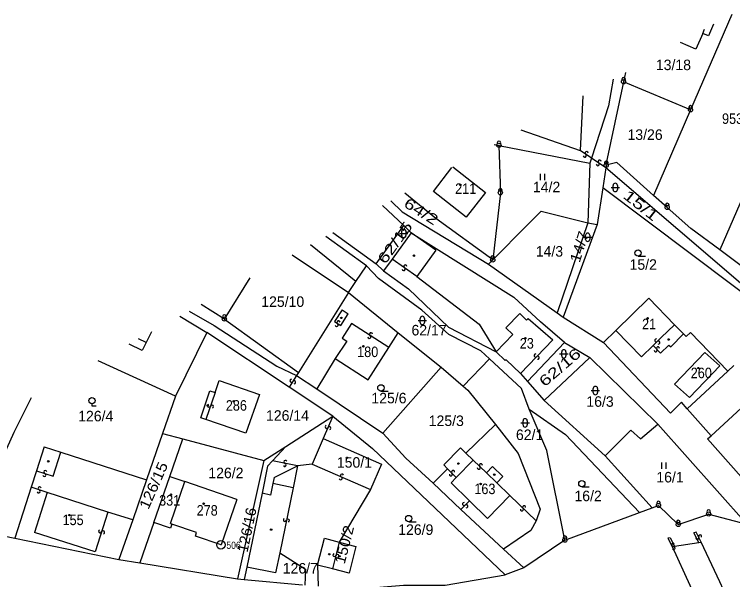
# Model space of a CAD drawing. Extents: x -680102 to -677253, y -1007548 to -1006096.
# Drawn here: x -679928 to -679757, y -1007092.8 to -1006958.4 of the extents above; entities that cross this region are included whole.
import ezdxf
from ezdxf.enums import TextEntityAlignment as Align

# ---------------------------------------------------------------- set-up
doc = ezdxf.new("R2010")
doc.units = 0
for name, color, linetype, lineweight in [('1', 7, 'Continuous', 25), ('24', 7, 'Continuous', 25), ('25', 7, 'Continuous', 25), ('4', 7, 'Continuous', 25)]:
    doc.layers.add(name, color=color, linetype=linetype, lineweight=lineweight)
for name, color, linetype in [('17', 7, 'Continuous'), ('18', 7, 'Continuous'), ('19', 7, 'Continuous')]:
    doc.layers.add(name, color=color, linetype=linetype)

msp = doc.modelspace()

# ---------------------------------------------------------------- linework, layer by layer
at = {"layer": '1'}
for p, q in [((-679757.23, -1006958.42), (-679767.04, -1006981.12)), ((-679765.74, -1006966.67), (-679769.4, -1006965.07)), ((-679739.2, -1006966.09), (-679760.08, -1007014.44)), ((-679782.51, -1006972.23), (-679782.98, -1006974.45)), ((-679782.98, -1006974.45), (-679787.08, -1006993.84)), ((-679785.46, -1006973.85), (-679786.54, -1006980.16)), ((-679767.04, -1006981.12), (-679782.98, -1006974.45)), ((-679792.7, -1006977.8), (-679793.34, -1006990.83)), ((-679767.04, -1006981.12), (-679775.83, -1007001.46)), ((-679807.4, -1006985.84), (-679793.34, -1006990.83)), ((-679791.04, -1006993.81), (-679791.46, -1007007.98)), ((-679828.25, -1007000.54), (-679823.88, -1006994.85)), ((-679787.16, -1006994.88), (-679787.94, -1006999.66)), ((-679787.11, -1006994.29), (-679787.16, -1006994.88)), ((-679745.57, -1007030.62), (-679787.16, -1006994.88)), ((-679827.65, -1007006.94), (-679835.04, -1007000.94)), ((-679802.58, -1007005.2), (-679805.94, -1007008.58)), ((-679802.58, -1007005.2), (-679791.46, -1007007.98)), ((-679767, -1007009.31), (-679772.59, -1007004.34)), ((-679814.11, -1007016.82), (-679827.65, -1007006.94)), ((-679841.89, -1007017.75), (-679835.31, -1007008.64)), ((-679805.94, -1007008.58), (-679814.11, -1007016.82)), ((-679791.46, -1007007.98), (-679798.76, -1007029.42)), ((-679789.24, -1007008.41), (-679797.34, -1007030.43)), ((-679791.46, -1007007.98), (-679789.24, -1007008.41)), ((-679852.14, -1007010.29), (-679841.89, -1007017.75)), ((-679844.15, -1007018.19), (-679853.83, -1007011.21)), ((-679846.67, -1007021.91), (-679857.49, -1007013.22)), ((-679841.89, -1007017.75), (-679840.1, -1007019.44)), ((-679814.11, -1007016.82), (-679815.13, -1007017.85)), ((-679877.98, -1007030.87), (-679871.82, -1007021.05)), ((-679848.46, -1007024.55), (-679836.61, -1007034.16)), ((-679776.99, -1007025.9), (-679784.84, -1007033.56)), ((-679770.86, -1007032.24), (-679776.99, -1007025.9)), ((-679877.98, -1007030.87), (-679883.47, -1007027.42)), ((-679886.39, -1007029.01), (-679880.44, -1007032.37)), ((-679877.98, -1007030.87), (-679860.36, -1007043.55)), ((-679797.34, -1007030.43), (-679787.78, -1007036.43)), ((-679880.44, -1007032.37), (-679865.47, -1007042.07)), ((-679797.03, -1007036.49), (-679802.76, -1007031.54)), ((-679768.73, -1007034.4), (-679770.86, -1007032.24)), ((-679836.61, -1007034.16), (-679826.39, -1007042.33)), ((-679784.84, -1007033.56), (-679787.78, -1007036.43)), ((-679768.1, -1007035.04), (-679768.73, -1007034.4)), ((-679767.07, -1007034.04), (-679768.1, -1007035.04)), ((-679758.16, -1007043.25), (-679767.07, -1007034.04)), ((-679797.03, -1007036.49), (-679805.84, -1007045.71)), ((-679797.03, -1007036.49), (-679790.99, -1007039.99)), ((-679771.83, -1007053.22), (-679787.78, -1007036.43)), ((-679811.13, -1007040.76), (-679813.31, -1007038.67)), ((-679790.99, -1007039.99), (-679801.85, -1007050.21)), ((-679770.82, -1007046.36), (-679763.61, -1007038.83)), ((-679851.62, -1007040.28), (-679855.97, -1007047.43)), ((-679851.62, -1007040.28), (-679843.76, -1007045.29)), ((-679821.17, -1007046.83), (-679814.91, -1007040.34)), ((-679865.47, -1007042.07), (-679860.84, -1007044.32)), ((-679840.27, -1007058.01), (-679826.39, -1007042.33)), ((-679860.84, -1007044.32), (-679855.97, -1007047.43)), ((-679767.31, -1007049.52), (-679770.82, -1007046.36)), ((-679855.97, -1007047.43), (-679840.27, -1007058.01)), ((-679805.44, -1007052.28), (-679807.27, -1007047.36)), ((-679889.6, -1007049.19), (-679892.68, -1007058.07)), ((-679769.21, -1007050.67), (-679771.83, -1007053.22)), ((-679767.86, -1007052.2), (-679769.21, -1007050.67)), ((-679801.21, -1007062.13), (-679805.44, -1007052.28)), ((-679805.44, -1007052.28), (-679796.8, -1007058.31)), ((-679852.14, -1007054), (-679842.76, -1007061.63)), ((-679813.45, -1007055.98), (-679820.49, -1007062.77)), ((-679778.92, -1007059.36), (-679774.85, -1007055.84)), ((-679892.68, -1007058.07), (-679896.5, -1007069.13)), ((-679892.68, -1007058.07), (-679887.85, -1007059.36)), ((-679840.27, -1007058.01), (-679834.81, -1007063.96)), ((-679779.22, -1007076.89), (-679796.8, -1007058.31)), ((-679781.21, -1007057.32), (-679787.33, -1007063.44)), ((-679778.92, -1007059.36), (-679781.21, -1007057.32)), ((-679890.96, -1007068.3), (-679887.85, -1007059.36)), ((-679887.85, -1007059.36), (-679868.58, -1007064.53)), ((-679854.48, -1007059.32), (-679857.12, -1007065.42)), ((-679854.48, -1007059.32), (-679840.61, -1007065.35)), ((-679920.86, -1007061.23), (-679922.71, -1007066.96)), ((-679842.76, -1007061.63), (-679811.14, -1007091.68)), ((-679825.73, -1007065.53), (-679821.77, -1007061.51)), ((-679821.77, -1007061.51), (-679820.49, -1007062.77)), ((-679796.94, -1007083.44), (-679801.21, -1007062.13)), ((-679868.58, -1007064.53), (-679874.84, -1007092.69)), ((-679857.12, -1007065.42), (-679860.55, -1007065.82)), ((-679840.61, -1007065.35), (-679843.2, -1007071.44)), ((-679824.85, -1007066.5), (-679825.73, -1007065.53)), ((-679867.68, -1007065.87), (-679869.01, -1007072.3)), ((-679860.55, -1007065.82), (-679861.62, -1007070.99)), ((-679824.85, -1007066.5), (-679828.32, -1007069.93)), ((-679896.5, -1007069.13), (-679899.8, -1007078.65)), ((-679890.8, -1007079.51), (-679887.36, -1007069.52)), ((-679875.03, -1007073.76), (-679887.36, -1007069.52)), ((-679866.41, -1007070.01), (-679866.97, -1007072.72)), ((-679861.62, -1007070.99), (-679866.41, -1007070.01)), ((-679866.97, -1007072.72), (-679869.01, -1007072.3)), ((-679843.2, -1007071.44), (-679850.63, -1007083.92)), ((-679776.19, -1007075.77), (-679774.66, -1007075.2)), ((-679821.69, -1007076.17), (-679811.59, -1007085.56)), ((-679899.8, -1007078.65), (-679903.06, -1007088.07)), ((-679894.78, -1007079.26), (-679898.13, -1007088.88)), ((-679890.8, -1007079.51), (-679890.45, -1007079.63)), ((-679805.07, -1007081.19), (-679811.59, -1007085.56)), ((-679811.59, -1007085.56), (-679806.75, -1007090.06)), ((-679864.82, -1007086.46), (-679865.84, -1007091.22)), ((-679864.82, -1007086.46), (-679858.64, -1007090.34)), ((-679903.06, -1007088.07), (-679898.13, -1007088.88)), ((-679898.13, -1007088.88), (-679874.84, -1007092.69)), ((-679855.79, -1007089.38), (-679855.63, -1007094.38)), ((-679865.84, -1007091.22), (-679872.6, -1007089.85)), ((-679858.64, -1007090.34), (-679858.85, -1007094.13))]:
    msp.add_line(p, q, dxfattribs=at)
for points in [[(-679761.54, -1006960.77), (-679762.75, -1006963.55), (-679764.12, -1006962.95), (-679765.74, -1006966.67)], [(-679786.54, -1006980.16), (-679790.64, -1006992.6), (-679791.04, -1006993.81)], [(-679812.64, -1006989.57), (-679812.29, -1007000.85), (-679814.11, -1007016.82)], [(-679813.81, -1006989.34), (-679812.64, -1006989.57), (-679791.04, -1006993.81)], [(-679784.58, -1006993.66), (-679787.11, -1006994.29), (-679787.08, -1006993.84)], [(-679772.59, -1007004.34), (-679775.83, -1007001.46), (-679784.58, -1006993.66)], [(-679823.61, -1006994.7), (-679815.81, -1007000.75), (-679820.44, -1007006.65), (-679828.25, -1007000.54)], [(-679736.11, -1007038.63), (-679787.94, -1006999.66), (-679789.24, -1007008.41)], [(-679840.34, -1007003.84), (-679835.31, -1007008.64), (-679833.52, -1007010.34)], [(-679838.34, -1007002.75), (-679835.67, -1007005.4), (-679815.13, -1007017.85)], [(-679833.52, -1007010.34), (-679838.08, -1007016.6), (-679840.1, -1007019.44)], [(-679833.52, -1007010.34), (-679809.11, -1007025.65), (-679802.76, -1007031.54)], [(-679751.46, -1007020.82), (-679760.08, -1007014.44), (-679767, -1007009.31)], [(-679861.83, -1007015.59), (-679848.46, -1007024.55), (-679860.36, -1007043.55), (-679860.84, -1007044.32)], [(-679848.46, -1007024.55), (-679846.67, -1007021.91), (-679844.15, -1007018.19)], [(-679816.96, -1007038.45), (-679824.59, -1007034.54), (-679830.95, -1007028.76), (-679841.32, -1007021.22), (-679844.15, -1007018.19)], [(-679840.1, -1007019.44), (-679834.14, -1007023.72), (-679824.68, -1007032.81), (-679813.31, -1007038.67)], [(-679815.13, -1007017.85), (-679798.76, -1007029.42), (-679797.34, -1007030.43)], [(-679888.55, -1007030.19), (-679882.19, -1007034.04), (-679889.6, -1007049.19), (-679908.05, -1007040.85)], [(-679895.36, -1007033.91), (-679896.63, -1007036.46), (-679897.58, -1007038.35), (-679900.66, -1007036.81)], [(-679852.14, -1007054), (-679862.57, -1007047.08), (-679882.19, -1007034.04)], [(-679843.76, -1007045.29), (-679838.85, -1007037.65), (-679836.61, -1007034.16)], [(-679807.27, -1007047.36), (-679814.91, -1007040.34), (-679816.96, -1007038.45)], [(-679790.99, -1007039.99), (-679774.85, -1007055.84), (-679753.61, -1007079.63)], [(-679767.31, -1007049.52), (-679760.09, -1007042.03), (-679763.61, -1007038.83)], [(-679807.5, -1007043.83), (-679810.92, -1007040.55), (-679811.13, -1007040.76)], [(-679826.39, -1007042.33), (-679821.17, -1007046.83), (-679820.03, -1007047.81)], [(-679767.86, -1007052.2), (-679758.16, -1007043.25), (-679756.75, -1007041.95)], [(-679807.5, -1007043.83), (-679805.84, -1007045.71), (-679801.85, -1007050.21)], [(-679820.03, -1007047.81), (-679813.45, -1007055.98), (-679808.1, -1007062.88)], [(-679965.15, -1007072.06), (-679965.26, -1007072.39), (-679961.39, -1007073.5), (-679938.19, -1007080.24), (-679928.04, -1007057.75), (-679923.88, -1007049.51)], [(-679801.85, -1007050.21), (-679787.33, -1007063.44), (-679776.19, -1007075.77)], [(-679762.97, -1007059.37), (-679762.16, -1007058.62), (-679767.86, -1007052.2)], [(-679868.58, -1007064.53), (-679863.36, -1007061.18), (-679852.14, -1007054)], [(-679747.35, -1007070.09), (-679750.83, -1007073.05), (-679752.52, -1007071.14), (-679762.97, -1007059.37)], [(-679920.86, -1007061.23), (-679916.88, -1007062.52), (-679896.5, -1007069.13)], [(-679867.68, -1007065.87), (-679866.51, -1007064.6), (-679863.36, -1007061.18)], [(-679808.1, -1007062.88), (-679802.82, -1007076.1), (-679803.79, -1007078.88), (-679805.07, -1007081.19)], [(-679834.81, -1007063.96), (-679828.32, -1007069.93), (-679821.69, -1007076.17)], [(-679922.71, -1007066.96), (-679923.98, -1007070.89), (-679927.88, -1007082.96)], [(-679884.59, -1007081.64), (-679890.45, -1007079.63), (-679890.8, -1007080.63), (-679894.78, -1007079.26), (-679890.96, -1007068.3), (-679887.36, -1007069.52)], [(-679869.01, -1007072.3), (-679872.6, -1007089.85), (-679873.26, -1007092.83)], [(-679875.03, -1007073.76), (-679878.75, -1007084.58), (-679884.89, -1007082.51), (-679884.59, -1007081.64)], [(-679796.94, -1007083.44), (-679779.22, -1007076.89), (-679776.19, -1007075.77)], [(-679774.66, -1007075.2), (-679769.96, -1007079.73), (-679762.72, -1007077.25)], [(-679762.72, -1007077.25), (-679753.61, -1007079.63), (-679744.06, -1007082.12)], [(-679933.72, -1007081.76), (-679927.88, -1007082.96), (-679903.06, -1007088.07)], [(-679796.94, -1007083.44), (-679806.75, -1007090.06), (-679811.14, -1007091.68)], [(-679874.84, -1007092.69), (-679873.26, -1007092.83), (-679859.4, -1007094.09)], [(-679846.67, -1007095.09), (-679835.35, -1007094.16), (-679825.42, -1007094.12), (-679811.14, -1007091.68)]]:
    msp.add_lwpolyline(points, dxfattribs=at)
for points in [[(-679879.19, -1007045.47), (-679869.64, -1007048.78), (-679872.84, -1007058.03), (-679882.38, -1007054.8), (-679883.59, -1007054.39), (-679881.41, -1007047.94), (-679880.18, -1007048.36)], [(-679854.16, -1007083.02), (-679850.63, -1007083.92), (-679846.67, -1007084.94), (-679848.3, -1007091.3), (-679852.27, -1007090.28), (-679855.79, -1007089.38)]]:
    msp.add_lwpolyline(points, close=True, dxfattribs=at)
at = {"layer": '24'}
for centre, radius in [((-679782.98, -1006974.45), 0.5), ((-679782.98, -1006974.45), 0.022), ((-679767.04, -1006981.12), 0.5), ((-679767.04, -1006981.12), 0.022), ((-679812.64, -1006989.57), 0.5), ((-679812.64, -1006989.57), 0.022), ((-679787.11, -1006994.29), 0.5), ((-679787.11, -1006994.29), 0.022), ((-679812.29, -1007000.85), 0.5), ((-679812.29, -1007000.85), 0.022), ((-679772.59, -1007004.34), 0.5), ((-679772.59, -1007004.34), 0.022), ((-679814.11, -1007016.82), 0.5), ((-679814.11, -1007016.82), 0.022), ((-679877.98, -1007030.87), 0.5), ((-679877.98, -1007030.87), 0.022), ((-679774.66, -1007075.2), 0.5), ((-679774.66, -1007075.2), 0.022), ((-679762.72, -1007077.25), 0.5), ((-679762.72, -1007077.25), 0.022), ((-679769.96, -1007079.73), 0.5), ((-679769.96, -1007079.73), 0.022), ((-679878.81, -1007084.57), 1), ((-679796.94, -1007083.44), 0.5), ((-679796.94, -1007083.44), 0.022), ((-679878.81, -1007084.57), 0.032)]:
    msp.add_circle(centre, radius, dxfattribs=at)
for centre in [(-679782.981, -1006973.887), (-679767.041, -1006980.557), (-679812.641, -1006989.007), (-679787.111, -1006993.727), (-679812.291, -1007000.287), (-679772.591, -1007003.777), (-679814.111, -1007016.257), (-679877.981, -1007030.307), (-679774.661, -1007074.637), (-679762.721, -1007076.687), (-679769.961, -1007079.167), (-679796.941, -1007082.877)]:
    msp.add_arc(centre, 0.437, 328.35109, 209.97456, dxfattribs=at)
at = {"layer": '25'}
for p, q in [((-679802.737, -1006997.845), (-679802.737, -1006996.345)), ((-679801.703, -1006997.845), (-679801.703, -1006996.345)), ((-679785.96, -1006999.58), (-679783.96, -1006999.58)), ((-679785.46, -1007000.08), (-679785.46, -1006999.08)), ((-679784.46, -1006999.08), (-679784.46, -1007000.08)), ((-679836.28, -1007010.51), (-679834.28, -1007010.51)), ((-679835.78, -1007011.01), (-679835.78, -1007010.01)), ((-679834.78, -1007010.01), (-679834.78, -1007011.01)), ((-679792.02, -1007011.93), (-679792.02, -1007010.93)), ((-679791.02, -1007010.93), (-679791.02, -1007011.93)), ((-679792.52, -1007011.43), (-679790.52, -1007011.43)), ((-679779.52, -1007015.9), (-679777.77, -1007015.9)), ((-679831.88, -1007031.21), (-679829.88, -1007031.21)), ((-679831.38, -1007031.71), (-679831.38, -1007030.71)), ((-679830.38, -1007030.71), (-679830.38, -1007031.71)), ((-679798.19, -1007039.16), (-679796.19, -1007039.16)), ((-679797.69, -1007039.66), (-679797.69, -1007038.66)), ((-679796.69, -1007038.66), (-679796.69, -1007039.66)), ((-679840.73, -1007047.99), (-679838.98, -1007047.99)), ((-679790.68, -1007047.88), (-679788.68, -1007047.88)), ((-679790.18, -1007048.38), (-679790.18, -1007047.38)), ((-679789.18, -1007047.38), (-679789.18, -1007048.38)), ((-679806.9, -1007056.07), (-679806.9, -1007055.07)), ((-679805.9, -1007055.07), (-679805.9, -1007056.07)), ((-679807.4, -1007055.57), (-679805.4, -1007055.57)), ((-679773.877, -1007066.485), (-679773.877, -1007064.985)), ((-679772.843, -1007066.485), (-679772.843, -1007064.985)), ((-679792.91, -1007070.75), (-679791.16, -1007070.75)), ((-679834.12, -1007079.07), (-679832.37, -1007079.07))]:
    msp.add_line(p, q, dxfattribs=at)
msp.add_lwpolyline([(-679909.49, -1007051.02), (-679909.49, -1007051.52), (-679908.467, -1007051.52)], dxfattribs=at)
for centre, radius in [((-679821.85, -1006998.96), 0.175), ((-679832.88, -1007015.8), 0.175), ((-679779.52, -1007015.15), 0.75), ((-679850.13, -1007030.6), 0.175), ((-679777.27, -1007030.71), 0.175), ((-679806.35, -1007035.44), 0.175), ((-679772.22, -1007035.74), 0.175), ((-679844.89, -1007037.36), 0.175), ((-679765.18, -1007042.54), 0.175), ((-679840.73, -1007047.24), 0.75), ((-679909.49, -1007050.27), 0.75), ((-679875.74, -1007050.43), 0.175), ((-679881.94, -1007051.43), 0.175), ((-679848.82, -1007063.87), 0.175), ((-679919.89, -1007064.7), 0.175), ((-679822.27, -1007065.24), 0.175), ((-679813.74, -1007067.88), 0.175), ((-679816.99, -1007070.09), 0.175), ((-679792.91, -1007070), 0.75), ((-679890.7, -1007072.64), 0.175), ((-679882.91, -1007074.78), 0.175), ((-679914.87, -1007077.49), 0.175), ((-679834.12, -1007078.32), 0.75), ((-679866.84, -1007080.93), 0.175), ((-679853.03, -1007086.81), 0.175), ((-679850.52, -1007087.29), 0.122)]:
    msp.add_circle(centre, radius, dxfattribs=at)
for centre, radius, start, end in [((-679792.194, -1006992.026), 0.368, 183.95115, 56.31038), ((-679791.785, -1006991.414), 0.369, 4.04139, 236.28428), ((-679789.104, -1006994.046), 0.368, 183.95115, 56.31038), ((-679788.695, -1006993.434), 0.369, 4.04139, 236.28428), ((-679784.96, -1006999.08), 0.5, 0.101, 180.00143), ((-679784.96, -1007000.08), 0.5, 180.10243, 0.00286), ((-679835.28, -1007010.01), 0.5, 0.101, 180.00143), ((-679791.52, -1007010.93), 0.5, 0.101, 180.00143), ((-679835.28, -1007011.01), 0.5, 180.10243, 0.00286), ((-679791.52, -1007011.93), 0.5, 180.10243, 0.00286), ((-679835.323, -1007018.98), 0.368, 182.22427, 54.62568), ((-679834.895, -1007018.38), 0.368, 2.1787, 234.37394), ((-679850.828, -1007031.653), 0.368, 3.87587, 236.65775), ((-679830.88, -1007030.71), 0.5, 0.101, 180.00143), ((-679851.234, -1007032.267), 0.369, 184.19771, 56.15841), ((-679830.88, -1007031.71), 0.5, 180.10243, 0.00286), ((-679843.481, -1007035.108), 0.368, 184.74679, 56.87209), ((-679843.077, -1007034.492), 0.368, 4.51811, 236.61336), ((-679775.215, -1007035.945), 0.368, 81.43684, 313.90079), ((-679774.706, -1007036.477), 0.369, 261.43294, 133.57458), ((-679797.19, -1007038.66), 0.5, 0.101, 180.00143), ((-679775.329, -1007038.312), 0.368, 171.2552, 43.21724), ((-679774.793, -1007037.807), 0.368, 350.98649, 223.45957), ((-679803.902, -1007039.551), 0.369, 83.45437, 315.33242), ((-679803.377, -1007040.067), 0.367, 263.01394, 135.66216), ((-679797.19, -1007039.66), 0.5, 180.10243, 0.00286), ((-679862.01, -1007045.5), 0.369, 95.13887, 326.93483), ((-679861.39, -1007045.898), 0.368, 274.76856, 147.43441), ((-679789.68, -1007047.38), 0.5, 0.101, 180.00143), ((-679789.68, -1007048.38), 0.5, 180.10243, 0.00286), ((-679881.627, -1007051.457), 0.368, 108.48491, 340.28908), ((-679880.933, -1007051.701), 0.368, 288.24541, 160.77745), ((-679806.4, -1007055.07), 0.5, 0.101, 180.00143), ((-679853.646, -1007056.507), 0.369, 103.50866, 335.3045), ((-679852.975, -1007056.811), 0.367, 283.20246, 155.73794), ((-679806.4, -1007056.07), 0.5, 180.10243, 0.00286), ((-679863.606, -1007065.569), 0.367, 205.90274, 78.04763), ((-679863.451, -1007064.85), 0.368, 25.93872, 257.79838), ((-679816.936, -1007065.684), 0.368, 353.77302, 226.32377), ((-679920.594, -1007067.261), 0.368, 19.24919, 251.61632), ((-679823.548, -1007067.261), 0.369, 352.6852, 224.8502), ((-679817.445, -1007066.216), 0.369, 173.9355, 45.95051), ((-679920.827, -1007067.959), 0.368, 199.46745, 71.47003), ((-679850.31, -1007068.767), 0.369, 193.96245, 65.79542), ((-679850.012, -1007068.094), 0.368, 14.09945, 246.22961), ((-679824.07, -1007067.78), 0.368, 172.83386, 45.00036), ((-679922.175, -1007071.859), 0.367, 199.56494, 71.76285), ((-679921.943, -1007071.16), 0.368, 19.51789, 251.51795), ((-679820.942, -1007074.861), 0.369, 83.29991, 315.33243), ((-679820.418, -1007075.378), 0.368, 262.83629, 135.44181), ((-679807.159, -1007076.132), 0.369, 173.30063, 45.42585), ((-679806.642, -1007075.608), 0.368, 353.10848, 225.44252), ((-679863.58, -1007078.651), 0.369, 115.73162, 347.62571), ((-679862.861, -1007078.807), 0.367, 295.40328, 167.89568), ((-679907.55, -1007081.373), 0.368, 109.5186, 341.32277), ((-679906.851, -1007081.605), 0.367, 289.39732, 161.76357), ((-679765.428, -1007082.916), 0.368, 154.38026, 26.84407), ((-679764.77, -1007082.585), 0.369, 334.76012, 206.8489), ((-679771.179, -1007084.566), 0.367, 45.39031, 277.66901), ((-679771.082, -1007085.295), 0.368, 225.55164, 97.49543), ((-679851.805, -1007087.003), 0.368, 112.87232, 344.72032), ((-679851.095, -1007087.195), 0.368, 292.21873, 165.01968)]:
    msp.add_arc(centre, radius, start, end, dxfattribs=at)
at = {"layer": '4'}
for p, q in [((-679764.12, -1006962.95), (-679763.68, -1006961.94)), ((-679827.66, -1007014.47), (-679833.52, -1007010.34)), ((-679827.66, -1007014.47), (-679832.15, -1007020.76)), ((-679832.15, -1007020.76), (-679838.08, -1007016.6)), ((-679849.97, -1007028.71), (-679851.77, -1007031.48)), ((-679850.29, -1007032.44), (-679848.5, -1007029.67)), ((-679849.97, -1007028.71), (-679848.5, -1007029.67)), ((-679851.77, -1007031.48), (-679850.29, -1007032.44)), ((-679896.63, -1007036.46), (-679898.4, -1007035.58)), ((-679848.8, -1007036.14), (-679851.62, -1007040.28)), ((-679799.78, -1007035.8), (-679807.5, -1007043.83)), ((-679860.84, -1007044.32), (-679862.57, -1007047.08)), ((-679880.18, -1007048.36), (-679882.38, -1007054.8)), ((-679762.16, -1007058.62), (-679749.79, -1007047.19)), ((-679852.14, -1007054), (-679854.48, -1007059.32)), ((-679820.49, -1007062.77), (-679818.77, -1007064.46)), ((-679860.55, -1007065.82), (-679866.51, -1007064.6)), ((-679857.12, -1007065.42), (-679843.2, -1007071.44)), ((-679866.11, -1007068.55), (-679860.55, -1007065.82)), ((-679822.78, -1007068.54), (-679824.85, -1007066.5)), ((-679814.15, -1007065.91), (-679815.6, -1007067.44)), ((-679814.15, -1007065.91), (-679811.7, -1007068.29)), ((-679866.11, -1007068.55), (-679866.41, -1007070.01)), ((-679811.7, -1007068.29), (-679813.15, -1007069.82)), ((-679920.14, -1007072.12), (-679923.15, -1007081.66)), ((-679861.62, -1007070.99), (-679864.82, -1007086.46)), ((-679819.66, -1007074.07), (-679821.69, -1007076.17)), ((-679810.01, -1007072.86), (-679815.32, -1007078.34)), ((-679765.71, -1007081.57), (-679766.25, -1007081.69)), ((-679765.05, -1007084), (-679766.25, -1007081.69)), ((-679764.49, -1007083.92), (-679765.71, -1007081.57)), ((-679850.63, -1007083.92), (-679852.27, -1007090.28)), ((-679771.88, -1007082.89), (-679772.42, -1007083.01)), ((-679772.42, -1007083.01), (-679771.41, -1007084.97)), ((-679771.88, -1007082.89), (-679770.85, -1007084.89)), ((-679765.05, -1007084), (-679764.49, -1007083.92))]:
    msp.add_line(p, q, dxfattribs=at)
for points in [[(-679787.16, -1006994.88), (-679790.64, -1006992.6), (-679793.34, -1006990.83)], [(-679832.15, -1007020.76), (-679817.33, -1007032.13), (-679813.31, -1007038.67)], [(-679813.31, -1007038.67), (-679809.32, -1007034.53), (-679810.96, -1007032.95), (-679807.68, -1007029.53), (-679806.04, -1007031.11), (-679805.69, -1007030.76), (-679799.78, -1007035.8)], [(-679838.85, -1007037.65), (-679847.71, -1007031.95), (-679849.94, -1007035.41), (-679848.8, -1007036.14)], [(-679775.93, -1007037.15), (-679773.99, -1007035.27), (-679770.86, -1007032.24)], [(-679784.84, -1007033.56), (-679778.74, -1007039.87), (-679775.93, -1007037.15), (-679774.19, -1007038.96), (-679772.23, -1007037.07), (-679771.75, -1007037.49), (-679768.73, -1007034.4)], [(-679922.71, -1007066.96), (-679918.71, -1007068.25), (-679916.88, -1007062.52)], [(-679824.01, -1007069.79), (-679822.78, -1007068.54), (-679818.77, -1007064.46)], [(-679818.77, -1007064.46), (-679815.6, -1007067.44), (-679813.15, -1007069.82)], [(-679815.32, -1007078.34), (-679819.66, -1007074.07), (-679824.01, -1007069.79)], [(-679813.15, -1007069.82), (-679810.01, -1007072.86), (-679803.79, -1007078.88)], [(-679899.8, -1007078.65), (-679905.68, -1007076.76), (-679920.14, -1007072.12), (-679923.98, -1007070.89)], [(-679905.68, -1007076.76), (-679908.72, -1007086.22), (-679923.15, -1007081.66)], [(-679771.41, -1007084.97), (-679770.85, -1007084.89), (-679765.05, -1007084)], [(-679756.57, -1007101), (-679760.09, -1007093.4), (-679764.49, -1007083.92)], [(-679771.41, -1007084.97), (-679767.18, -1007094.19), (-679762.95, -1007103.4)]]:
    msp.add_lwpolyline(points, dxfattribs=at)

# ---------------------------------------------------------------- texts
at = {"layer": '17', "width": 0.9}
msp.add_text('506', height=1.7, dxfattribs=at).set_placement((-679874.09, -1007085.52), align=Align.RIGHT)
at = {"layer": '18'}
for s, p in [('13/18', (-679771.11, -1006971.68)), ('13/26', (-679777.86, -1006988.27)), ('125/10', (-679864.09, -1007027.99))]:
    msp.add_text(s, height=2.5, dxfattribs=at).set_placement(p, align=Align.CENTER)
at = {"layer": '18', "width": 0.9}
msp.add_text('953', height=2.5, dxfattribs=at).set_placement((-679757.03, -1006984.47), align=Align.CENTER)
at = {"layer": '18'}
for s, p in [('14/2', (-679804.55, -1007000.73)), ('14/3', (-679803.87, -1007016.02)), ('15/2', (-679781.55, -1007019.16)), ('62/17', (-679833.45, -1007034.77)), ('125/6', (-679843, -1007050.92)), ('16/3', (-679791.83, -1007051.74)), ('126/4', (-679912.78, -1007055.2)), ('126/14', (-679868.07, -1007055.06)), ('125/3', (-679829.35, -1007056.31)), ('62/1', (-679808.59, -1007059.64)), ('126/2', (-679881.8, -1007068.72)), ('16/1', (-679775.18, -1007069.73)), ('16/2', (-679794.67, -1007074.19)), ('126/9', (-679836.61, -1007082.2)), ('126/7', (-679864.09, -1007091.39))]:
    msp.add_text(s, height=2.5, dxfattribs=at).set_placement(p)
for s, rotation, width, p in [('15/1', 321.603, 1.45, (-679783.32, -1007001.908)), ('64/2', 327.703, 1.35, (-679835.515, -1007003.988)), ('14/7', 72.601, 1.15, (-679793.441, -1007017.63)), ('126/15', 66.201, 1.15, (-679896.062, -1007076.337)), ('126/16', 78.101, 1.05, (-679872.494, -1007086.524))]:
    msp.add_text(s, height=2.5, rotation=rotation, dxfattribs=dict(at, width=width)).set_placement(p)
for s, rotation, width, p in [('62/15', 54, 1.35, (-679836.354, -1007013.416)), ('62/16', 40.7, 1.4, (-679797.32, -1007043.319))]:
    msp.add_text(s, height=2.5, rotation=rotation, dxfattribs=dict(at, width=width)).set_placement(p, align=Align.CENTER)
at = {"layer": '19', "width": 0.9}
for s, p in [('211', (-679823.06, -1007001.11)), ('21', (-679778.58, -1007033.31)), ('23', (-679807.68, -1007037.89)), ('180', (-679846.38, -1007039.92)), ('260', (-679766.99, -1007044.94)), ('286', (-679877.64, -1007052.67)), ('163', (-679818.49, -1007072.51)), ('278', (-679884.58, -1007077.62)), ('155', (-679916.49, -1007079.88))]:
    msp.add_text(s, height=2.5, dxfattribs=at).set_placement(p)
at = {"layer": '19'}
msp.add_text('150/1', height=2.5, dxfattribs=at).set_placement((-679851.21, -1007066.22))
at = {"layer": '19', "width": 0.9}
msp.add_text('331', height=2.5, dxfattribs=at).set_placement((-679891, -1007075.24), align=Align.CENTER)
at = {"layer": '19', "width": 1.1}
msp.add_text('150/2', height=2.5, rotation=75.601, dxfattribs=at).set_placement((-679849.363, -1007089.277))

doc.saveas('drawing.dxf')
